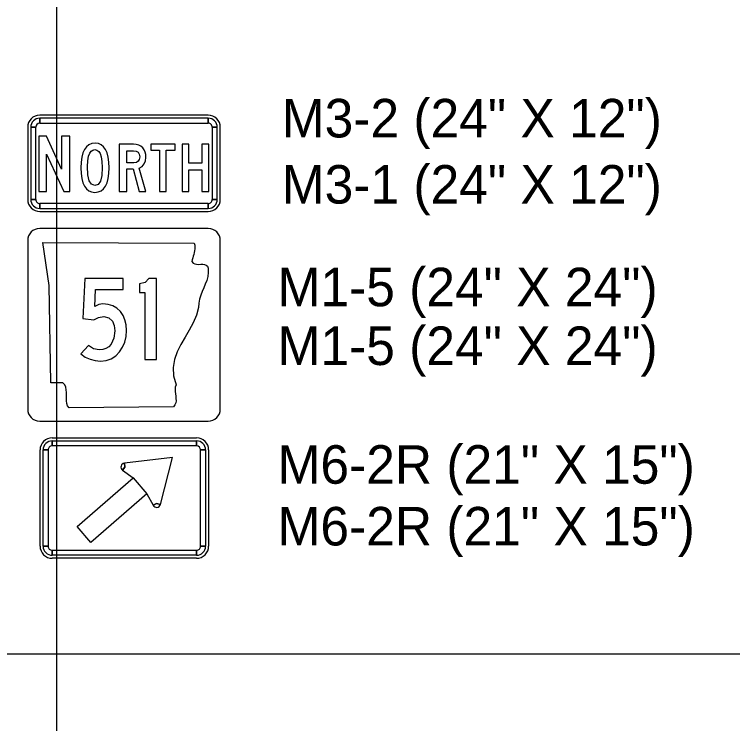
# Model space of a CAD drawing. Extents: x 1001568 to 1002149, y 1840825 to 1841423.
# Drawn here: x 1001905.21 to 1001912.67, y 1841194.75 to 1841202.11 of the extents above; entities that cross this region are included whole.
import ezdxf

# ---------------------------------------------------------------- set-up
doc = ezdxf.new("R2010")
doc.units = 0
for name, color, linetype in [('40', 7, 'Continuous'), ('R_No Plot', 7, 'Continuous'), ('SIGNS', 7, 'Continuous')]:
    doc.layers.add(name, color=color, linetype=linetype)

msp = doc.modelspace()

# ---------------------------------------------------------------- linework, layer by layer
at = {"layer": 'R_No Plot'}
for p, q in [((1001905.6501, 1841210.6666), (1001905.6501, 1841148.1274)), ((1001886.4111, 1841195.4691), (1001982.1327, 1841195.4691))]:
    msp.add_line(p, q, dxfattribs=at)
at = {"layer": 'SIGNS'}
for p, q in [((1001907.2246, 1841201.0614), (1001905.4746, 1841201.0614)), ((1001905.4746, 1841200.9781), (1001905.4746, 1841201.0302)), ((1001907.2246, 1841201.0302), (1001907.2246, 1841200.9781)), ((1001905.3496, 1841200.9364), (1001905.3496, 1841200.1864)), ((1001905.3808, 1841200.9364), (1001905.4329, 1841200.9364)), ((1001907.2663, 1841200.9364), (1001907.3183, 1841200.9364)), ((1001907.3496, 1841200.1864), (1001907.3496, 1841200.9364)), ((1001905.4329, 1841200.1864), (1001905.3808, 1841200.1864)), ((1001907.3183, 1841200.1864), (1001907.2663, 1841200.1864)), ((1001905.4746, 1841200.0927), (1001905.4746, 1841200.1447)), ((1001907.2246, 1841200.1447), (1001907.2246, 1841200.0927)), ((1001905.4746, 1841200.0614), (1001907.2246, 1841200.0614)), ((1001907.2246, 1841199.8858), (1001905.4746, 1841199.8858)), ((1001905.3496, 1841199.7608), (1001905.3496, 1841198.0108)), ((1001907.3496, 1841198.0108), (1001907.3496, 1841199.7608)), ((1001905.3496, 1841198.0108), (1001905.3496, 1841198.0108)), ((1001905.4746, 1841197.8858), (1001907.2246, 1841197.8858)), ((1001905.6035, 1841197.712), (1001907.1035, 1841197.712)), ((1001905.6035, 1841197.6808), (1001905.6035, 1841197.6287)), ((1001907.1035, 1841197.6287), (1001907.1035, 1841197.6808)), ((1001905.4785, 1841196.587), (1001905.4785, 1841197.587)), ((1001905.5618, 1841197.587), (1001905.5098, 1841197.587)), ((1001907.1973, 1841197.587), (1001907.1452, 1841197.587)), ((1001907.2285, 1841197.587), (1001907.2285, 1841196.587)), ((1001906.3354, 1841197.3757), (1001906.3599, 1841197.4094)), ((1001906.3599, 1841197.4094), (1001906.3536, 1841197.4506)), ((1001906.688, 1841197.0321), (1001906.6512, 1841197.0125)), ((1001906.7279, 1841197.0201), (1001906.688, 1841197.0321)), ((1001905.5098, 1841196.587), (1001905.5618, 1841196.587)), ((1001907.1452, 1841196.587), (1001907.1973, 1841196.587)), ((1001905.6035, 1841196.5454), (1001905.6035, 1841196.4933)), ((1001907.1035, 1841196.4933), (1001907.1035, 1841196.5454)), ((1001907.1035, 1841196.462), (1001905.6035, 1841196.462))]:
    msp.add_line(p, q, dxfattribs=at)
for points in [[(1001907.2246, 1841201.0302), (1001905.4746, 1841201.0302), (1001905.4746, 1841200.9781), (1001907.2246, 1841200.9781), (1001907.2246, 1841201.0302), (1001907.2246, 1841201.0302)], [(1001905.3808, 1841200.9364), (1001905.3808, 1841200.1864), (1001905.4329, 1841200.1864), (1001905.4329, 1841200.9364), (1001905.3808, 1841200.9364), (1001905.3808, 1841200.9364)], [(1001907.3183, 1841200.1864), (1001907.3183, 1841200.9364), (1001907.2663, 1841200.9364), (1001907.2663, 1841200.1864), (1001907.3183, 1841200.1864), (1001907.3183, 1841200.1864)], [(1001905.4649, 1841200.2697), (1001905.5434, 1841200.2697), (1001905.5434, 1841200.6562), (1001905.724, 1841200.2697), (1001905.7879, 1841200.2697), (1001905.7879, 1841200.8418), (1001905.7005, 1841200.8418), (1001905.7005, 1841200.5005), (1001905.5434, 1841200.8418), (1001905.4649, 1841200.8418)], [(1001906.7168, 1841200.2697), (1001906.788, 1841200.2697), (1001906.788, 1841200.6985), (1001906.8795, 1841200.6985), (1001906.8795, 1841200.7601), (1001906.6273, 1841200.7601), (1001906.6273, 1841200.6985), (1001906.7168, 1841200.6985)], [(1001906.9543, 1841200.2697), (1001907.0215, 1841200.2697), (1001907.0215, 1841200.4948), (1001907.1562, 1841200.4948), (1001907.1562, 1841200.2697), (1001907.2311, 1841200.2697), (1001907.2311, 1841200.7601), (1001907.1562, 1841200.7601), (1001907.1562, 1841200.5634), (1001907.0215, 1841200.5634), (1001907.0215, 1841200.7601), (1001906.9543, 1841200.7601)], [(1001905.4746, 1841200.0927), (1001907.2246, 1841200.0927), (1001907.2246, 1841200.1447), (1001905.4746, 1841200.1447), (1001905.4746, 1841200.0927), (1001905.4746, 1841200.0927)], [(1001907.0795, 1841199.7314), (1001907.0842, 1841199.7123), (1001907.0859, 1841199.6928), (1001907.0852, 1841199.6737), (1001907.0828, 1841199.6546), (1001907.0788, 1841199.6356), (1001907.0741, 1841199.6168), (1001907.0684, 1841199.5978), (1001907.0628, 1841199.5794), (1001907.0574, 1841199.561), (1001907.0524, 1841199.5427), (1001907.0664, 1841199.5265), (1001907.0838, 1841199.5174), (1001907.1035, 1841199.5133), (1001907.125, 1841199.5129), (1001907.1463, 1841199.5137), (1001907.1671, 1841199.514), (1001907.1861, 1841199.5118), (1001907.2028, 1841199.5056), (1001907.2158, 1841199.4935), (1001907.2239, 1841199.4733), (1001907.2245, 1841199.4278), (1001907.2188, 1841199.3852), (1001907.2082, 1841199.3448), (1001907.1938, 1841199.3063), (1001907.1781, 1841199.2681), (1001907.162, 1841199.2303), (1001907.147, 1841199.1917), (1001907.135, 1841199.1521), (1001907.1266, 1841199.1106), (1001907.1246, 1841199.0665), (1001907.1025, 1841198.9843), (1001907.0688, 1841198.9061), (1001907.028, 1841198.8305), (1001906.9839, 1841198.7556), (1001906.9408, 1841198.6811), (1001906.903, 1841198.6051), (1001906.875, 1841198.5265), (1001906.8606, 1841198.4439), (1001906.8639, 1841198.3565), (1001906.8897, 1841198.2629), (1001906.882, 1841198.2398), (1001906.8793, 1841198.2159), (1001906.88, 1841198.1921), (1001906.883, 1841198.1678), (1001906.8863, 1841198.144), (1001906.889, 1841198.1205), (1001906.8897, 1841198.0974), (1001906.8863, 1841198.0757), (1001906.878, 1841198.0544), (1001906.8626, 1841198.0346), (1001905.7789, 1841198.0247), (1001905.7642, 1841198.0445), (1001905.7558, 1841198.0683), (1001905.7522, 1841198.0948), (1001905.7518, 1841198.123), (1001905.7525, 1841198.1528), (1001905.7528, 1841198.1822), (1001905.7508, 1841198.2112), (1001905.7451, 1841198.238), (1001905.7341, 1841198.2622), (1001905.7157, 1841198.2827), (1001905.5894, 1841198.2827), (1001905.5714, 1841199.2945), (1001905.5079, 1841199.7413), (1001907.0795, 1841199.7314), (1001907.0795, 1841199.7314)], [(1001905.8999, 1841198.5836), (1001905.9475, 1841198.5506), (1001905.9975, 1841198.5273), (1001906.0497, 1841198.5135), (1001906.1044, 1841198.5089), (1001906.1637, 1841198.5148), (1001906.2168, 1841198.533), (1001906.2638, 1841198.5634), (1001906.3047, 1841198.6065), (1001906.3354, 1841198.654), (1001906.3573, 1841198.7066), (1001906.3705, 1841198.7641), (1001906.3751, 1841198.8271), (1001906.3713, 1841198.8845), (1001906.3596, 1841198.9367), (1001906.3403, 1841198.9828), (1001906.3132, 1841199.0233), (1001906.2766, 1841199.0579), (1001906.2343, 1841199.0828), (1001906.1853, 1841199.0978), (1001906.1307, 1841199.1029), (1001906.0894, 1841199.0962), (1001906.0458, 1841199.0761), (1001906.055, 1841199.2515), (1001906.3421, 1841199.2515), (1001906.3421, 1841199.3671), (1001905.9414, 1841199.3671), (1001905.9209, 1841198.9511), (1001906.0373, 1841198.9361), (1001906.0863, 1841198.9621), (1001906.1392, 1841198.9709), (1001906.1912, 1841198.9591), (1001906.2292, 1841198.9243), (1001906.2488, 1841198.8783), (1001906.2555, 1841198.8213), (1001906.2454, 1841198.7466), (1001906.2155, 1841198.6854), (1001906.191, 1841198.6584), (1001906.1623, 1841198.6395), (1001906.1291, 1841198.6279), (1001906.0917, 1841198.6243), (1001906.0344, 1841198.636), (1001905.9805, 1841198.6713)], [(1001906.5644, 1841198.5253), (1001906.6874, 1841198.5253), (1001906.6874, 1841199.3671), (1001906.606, 1841199.3671), (1001906.5678, 1841199.3258), (1001906.5093, 1841199.3103), (1001906.5093, 1841199.2222), (1001906.5644, 1841199.2222)], [(1001905.6035, 1841197.6808), (1001907.1035, 1841197.6808), (1001907.1035, 1841197.6287), (1001905.6035, 1841197.6287), (1001905.6035, 1841197.6808), (1001905.6035, 1841197.6808)], [(1001905.5098, 1841196.587), (1001905.5098, 1841197.587), (1001905.5618, 1841197.587), (1001905.5618, 1841196.587), (1001905.5098, 1841196.587), (1001905.5098, 1841196.587)], [(1001907.1973, 1841197.587), (1001907.1973, 1841196.587), (1001907.1452, 1841196.587), (1001907.1452, 1841197.587), (1001907.1973, 1841197.587), (1001907.1973, 1841197.587)], [(1001906.8541, 1841197.5078), (1001906.3536, 1841197.4506), (1001906.3599, 1841197.4094), (1001906.3354, 1841197.3757), (1001906.4443, 1841197.2965), (1001906.5878, 1841197.1314), (1001906.6512, 1841197.0125), (1001906.688, 1841197.0321), (1001906.7279, 1841197.0201), (1001906.8541, 1841197.5078)], [(1001906.0061, 1841196.6257), (1001905.8626, 1841196.7908), (1001906.4443, 1841197.2965), (1001906.5878, 1841197.1314), (1001906.0061, 1841196.6257)], [(1001907.1035, 1841196.4933), (1001905.6035, 1841196.4933), (1001905.6035, 1841196.5454), (1001907.1035, 1841196.5454), (1001907.1035, 1841196.4933), (1001907.1035, 1841196.4933)]]:
    msp.add_lwpolyline(points, close=True, dxfattribs=at)
for points in [[(1001906.1948, 1841200.5156), (1001906.1924, 1841200.575), (1001906.1857, 1841200.6267), (1001906.1744, 1841200.6703), (1001906.1586, 1841200.7061), (1001906.138, 1841200.7338), (1001906.1132, 1841200.7538), (1001906.0838, 1841200.7656), (1001906.05, 1841200.7697), (1001906.0155, 1841200.7656), (1001905.9855, 1841200.7538), (1001905.9603, 1841200.7338), (1001905.9397, 1841200.7061), (1001905.9237, 1841200.6703), (1001905.9122, 1841200.6267), (1001905.9053, 1841200.575), (1001905.9031, 1841200.5156), (1001905.9052, 1841200.4555), (1001905.9119, 1841200.4037), (1001905.9232, 1841200.3597), (1001905.939, 1841200.3239), (1001905.9591, 1841200.2959), (1001905.9839, 1841200.276), (1001906.0132, 1841200.2641), (1001906.047, 1841200.2602), (1001906.0816, 1841200.2641), (1001906.1116, 1841200.276), (1001906.137, 1841200.2959), (1001906.1578, 1841200.3239), (1001906.174, 1841200.3597), (1001906.1855, 1841200.4037), (1001906.1924, 1841200.4555), (1001906.1948, 1841200.5156)], [(1001906.3009, 1841200.2697), (1001906.3778, 1841200.2697), (1001906.3778, 1841200.5032), (1001906.4433, 1841200.5032), (1001906.5075, 1841200.2697), (1001906.5778, 1841200.2697), (1001906.5065, 1841200.5114), (1001906.5369, 1841200.5286), (1001906.5601, 1841200.5556), (1001906.5733, 1841200.587), (1001906.5778, 1841200.6228), (1001906.5757, 1841200.6522), (1001906.5694, 1841200.6787), (1001906.559, 1841200.7018), (1001906.5446, 1841200.7218), (1001906.5255, 1841200.7385), (1001906.5029, 1841200.7505), (1001906.4769, 1841200.7577), (1001906.4476, 1841200.7601), (1001906.3009, 1841200.7601), (1001906.3009, 1841200.2697)], [(1001906.1242, 1841200.5179), (1001906.1194, 1841200.4362), (1001906.105, 1841200.378), (1001906.0811, 1841200.343), (1001906.0477, 1841200.3314), (1001906.0138, 1841200.3438), (1001905.9896, 1841200.3811), (1001905.9752, 1841200.4431), (1001905.9703, 1841200.5302), (1001905.9734, 1841200.5881), (1001905.9827, 1841200.6361), (1001905.9938, 1841200.6656), (1001906.0084, 1841200.6869), (1001906.0263, 1841200.6995), (1001906.0477, 1841200.7039), (1001906.0688, 1841200.6992), (1001906.0867, 1841200.6853), (1001906.1012, 1841200.662), (1001906.1125, 1841200.6297), (1001906.1212, 1841200.5788), (1001906.1242, 1841200.5179)], [(1001906.3778, 1841200.5678), (1001906.3778, 1841200.6928), (1001906.4498, 1841200.6928), (1001906.475, 1841200.6884), (1001906.4951, 1841200.6758), (1001906.5081, 1841200.6558), (1001906.5124, 1841200.63), (1001906.5085, 1841200.6026), (1001906.4973, 1841200.5833), (1001906.4785, 1841200.5716), (1001906.4522, 1841200.5678), (1001906.3778, 1841200.5678)], [(1001905.4746, 1841199.8858), (1001905.4746, 1841199.8858)], [(1001907.2246, 1841199.8858), (1001907.2246, 1841199.8858)], [(1001905.3496, 1841199.7608), (1001905.3496, 1841199.7608)], [(1001905.4746, 1841197.8858), (1001905.4746, 1841197.8858)], [(1001907.2246, 1841197.8858), (1001907.2246, 1841197.8858)]]:
    msp.add_lwpolyline(points, dxfattribs=at)
for centre, radius, start, end in [((1001905.4746, 1841200.9364), 0.125, 90.00021, 179.99985), ((1001907.2246, 1841200.9364), 0.125, 360, 90.00021), ((1001905.4746, 1841200.9364), 0.0937, 90.00021, 179.99985), ((1001907.2246, 1841200.9364), 0.0937, 360, 90.00021), ((1001905.4746, 1841200.9364), 0.0417, 90.00021, 179.99985), ((1001907.2246, 1841200.9364), 0.0417, 360, 90.00021), ((1001905.4746, 1841200.1864), 0.125, 179.99985, 270.00006), ((1001905.4746, 1841200.1864), 0.0937, 179.99985, 270.00006), ((1001905.4746, 1841200.1864), 0.0417, 179.99985, 270.00006), ((1001907.2246, 1841200.1864), 0.125, 270.00006, 0.00027), ((1001907.2246, 1841200.1864), 0.0937, 270.00006, 0.00027), ((1001907.2246, 1841200.1864), 0.0417, 270.00006, 0.00027), ((1001905.4746, 1841199.7608), 0.125, 90.00021, 179.99985), ((1001907.2246, 1841199.7608), 0.125, 0, 90), ((1001905.4746, 1841198.0108), 0.125, 180, 270), ((1001907.2246, 1841198.0108), 0.125, 270.00006, 0.00027), ((1001905.6035, 1841197.587), 0.125, 89.99979, 180), ((1001907.1035, 1841197.587), 0.125, 0.00015, 89.99979), ((1001905.6035, 1841197.587), 0.0937, 89.99979, 180), ((1001905.6035, 1841197.587), 0.0417, 89.99979, 180), ((1001907.1035, 1841197.587), 0.0937, 0.00015, 89.99979), ((1001907.1035, 1841197.587), 0.0417, 0.00015, 89.99979), ((1001906.3599, 1841197.4094), 0.0417, 98.72435, 233.95041), ((1001906.688, 1841197.0321), 0.0417, 208.04986, 343.27592), ((1001905.6035, 1841196.587), 0.125, 179.99973, 269.99994), ((1001905.6035, 1841196.587), 0.0937, 179.99973, 269.99994), ((1001905.6035, 1841196.587), 0.0417, 179.99973, 269.99994), ((1001907.1035, 1841196.587), 0.0937, 269.99994, 0.00015), ((1001907.1035, 1841196.587), 0.0417, 269.99994, 0.00015), ((1001907.1035, 1841196.587), 0.125, 269.99994, 0.00015)]:
    msp.add_arc(centre, radius, start, end, dxfattribs=at)

# ---------------------------------------------------------------- texts
at = {"layer": '40'}
for s, p in [('M3-2 (24" X 12")', (1001907.9875, 1841200.8301)), ('M3-1 (24" X 12")', (1001907.9875, 1841200.1435)), ('M1-5 (24" X 24")', (1001907.9436, 1841199.0778)), ('M1-5 (24" X 24")', (1001907.9436, 1841198.468)), ('M6-2R (21" X 15")', (1001907.9436, 1841197.2359)), ('M6-2R (21" X 15")', (1001907.9436, 1841196.595))]:
    msp.add_text(s, height=0.4, rotation=0, dxfattribs=at).set_placement(p)

doc.saveas('drawing.dxf')
